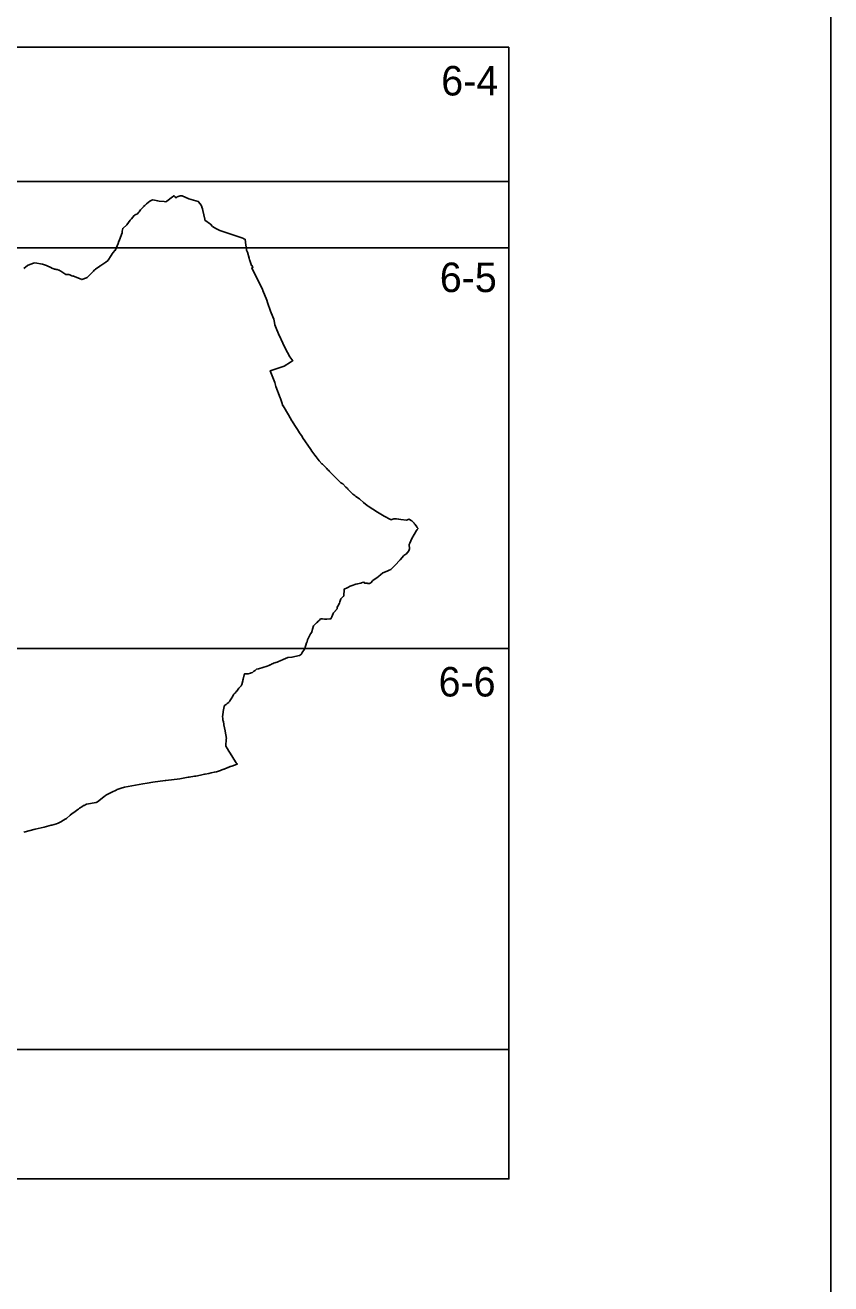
# Model space of a CAD drawing. Extents: x -449577 to -436680, y -1132317 to -1125726.
# Drawn here: x -443806.9 to -443555.6, y -1130335.5 to -1129943.1 of the extents above; entities that cross this region are included whole.
import ezdxf

# ---------------------------------------------------------------- set-up
doc = ezdxf.new("R2010")
doc.units = 0
for name, color, linetype in [('Vrstva 1', 7, 'Continuous'), ('Vrstva 10', 7, 'Continuous'), ('Vrstva 4', 7, 'Continuous')]:
    doc.layers.add(name, color=color, linetype=linetype)

msp = doc.modelspace()

# ---------------------------------------------------------------- linework, layer by layer
at = {"layer": 'Vrstva 1'}
msp.add_lwpolyline([(-445040.56, -1129648.53), (-445040.56, -1130698.53), (-443555.56, -1130698.53), (-443555.56, -1129648.53)], close=True, dxfattribs=at)
msp.add_lwpolyline([(-443807.27, -1130194.65), (-443803.73, -1130193.78), (-443800.96, -1130193.11), (-443800.29, -1130192.9), (-443798.8, -1130192.54), (-443798.59, -1130192.48), (-443797.16, -1130192.09), (-443796.56, -1130191.83), (-443796.34, -1130191.73), (-443796.18, -1130191.67), (-443795.36, -1130191.22), (-443795.3, -1130191.18), (-443793.99, -1130190.4), (-443792.84, -1130189.35), (-443792.19, -1130188.85), (-443792.06, -1130188.74), (-443792.04, -1130188.73), (-443791.88, -1130188.6), (-443791.73, -1130188.5), (-443790.93, -1130187.94), (-443790.87, -1130187.9), (-443790.8, -1130187.85), (-443790.29, -1130187.5), (-443789.92, -1130187.24), (-443789.26, -1130186.78), (-443788.67, -1130186.37), (-443788.51, -1130186.4), (-443788.5, -1130186.4), (-443788.48, -1130186.38), (-443787.75, -1130185.99), (-443784.79, -1130185.41), (-443784.37, -1130185.26), (-443782.34, -1130183.63), (-443781.87, -1130183.29), (-443781.84, -1130183.27), (-443781.48, -1130183.01), (-443781.3, -1130182.89), (-443779.91, -1130182.19), (-443778.5, -1130181.55), (-443778.2, -1130181.4), (-443776.94, -1130180.94), (-443775.94, -1130180.69), (-443770.23, -1130179.63), (-443768.81, -1130179.37), (-443767.1, -1130179.12), (-443763.23, -1130178.55), (-443762.99, -1130178.52), (-443758.69, -1130178), (-443758.16, -1130177.94), (-443756.01, -1130177.58), (-443755.69, -1130177.53), (-443754.03, -1130177.26), (-443753.63, -1130177.19), (-443752.22, -1130176.9), (-443750.93, -1130176.63), (-443750.72, -1130176.59), (-443749.55, -1130176.36), (-443748.88, -1130176.23), (-443748.86, -1130176.23), (-443747.95, -1130176.02), (-443747.88, -1130176), (-443747.23, -1130175.84), (-443746.88, -1130175.73), (-443745.99, -1130175.44), (-443745.55, -1130175.29), (-443744.9, -1130175.05), (-443744.78, -1130175.01), (-443743.69, -1130174.52), (-443743.69, -1130174.52), (-443743.57, -1130174.48), (-443742.92, -1130174.25), (-443742.83, -1130174.22), (-443742.4, -1130174.06), (-443740.74, -1130173.48), (-443740.76, -1130173.43), (-443740.87, -1130173.26), (-443741.03, -1130173.03), (-443741.25, -1130172.71), (-443742.95, -1130170.07), (-443743.16, -1130169.72), (-443743.33, -1130169.45), (-443743.77, -1130168.74), (-443744.3, -1130167.89), (-443744.14, -1130165.53), (-443744.13, -1130165.44), (-443744.52, -1130163.14), (-443744.52, -1130163.12), (-443744.53, -1130163.1), (-443744.53, -1130163.1), (-443744.53, -1130163.07), (-443744.94, -1130161.24), (-443744.95, -1130161.05), (-443745.01, -1130160.25), (-443745.11, -1130159.97), (-443745.12, -1130159.95), (-443745.23, -1130159.73), (-443745.27, -1130159.65), (-443745.28, -1130159.27), (-443745.31, -1130158.57), (-443745.26, -1130158.08), (-443745.26, -1130158.06), (-443745.17, -1130157.2), (-443745.15, -1130157.09), (-443744.86, -1130155.45), (-443744.78, -1130155.37), (-443744.48, -1130155.03), (-443744.42, -1130154.96), (-443744.16, -1130154.84), (-443744.1, -1130154.78), (-443743.84, -1130154.58), (-443743.61, -1130154.4), (-443743.4, -1130154.24), (-443743.34, -1130154.2), (-443743.26, -1130154.07), (-443743.18, -1130153.95), (-443743.07, -1130153.78), (-443742.85, -1130153.45), (-443742.43, -1130152.8), (-443742.3, -1130152.55), (-443742.29, -1130152.54), (-443742.15, -1130152.25), (-443742.1, -1130152.16), (-443741.92, -1130151.83), (-443741.78, -1130151.68), (-443741.48, -1130151.37), (-443741.31, -1130151.19), (-443741.03, -1130150.84), (-443740.9, -1130150.67), (-443740.21, -1130149.82), (-443739.55, -1130149.01), (-443739.26, -1130148.65), (-443739.02, -1130147.48), (-443738.96, -1130147.25), (-443738.89, -1130146.97), (-443738.57, -1130145.66), (-443738.49, -1130145.38), (-443738.49, -1130145.35), (-443738.47, -1130145.3), (-443738.31, -1130145.29), (-443738.29, -1130145.29), (-443738.05, -1130145.29), (-443737.36, -1130145.27), (-443737.35, -1130145.27), (-443737.32, -1130145.27), (-443736.64, -1130145.09), (-443736.44, -1130145.03), (-443736.02, -1130144.92), (-443736, -1130144.91), (-443735.94, -1130144.85), (-443735.64, -1130144.57), (-443735.52, -1130144.49), (-443735.18, -1130144.23), (-443734.76, -1130143.91), (-443734.69, -1130143.89), (-443734.13, -1130143.73), (-443731.43, -1130142.97), (-443730.84, -1130142.7), (-443730.51, -1130142.54), (-443730.46, -1130142.52), (-443730.36, -1130142.47), (-443730, -1130142.29), (-443729.95, -1130142.27), (-443729.92, -1130142.25), (-443729.91, -1130142.25), (-443729.88, -1130142.23), (-443729.57, -1130142.08), (-443729.51, -1130142.04), (-443729.4, -1130141.99), (-443728.32, -1130141.66), (-443727.89, -1130141.48), (-443727.37, -1130141.26), (-443726.36, -1130140.85), (-443724.94, -1130140.22), (-443724.8, -1130140.21), (-443723.67, -1130140.16), (-443721.27, -1130139.6), (-443720.74, -1130139.2), (-443720.67, -1130139.08), (-443720.58, -1130138.9), (-443720.32, -1130138.39), (-443719.97, -1130137.96), (-443719.95, -1130137.93), (-443719.74, -1130137.64), (-443719.63, -1130137.48), (-443719.62, -1130137.47), (-443719.08, -1130135.69), (-443719.07, -1130135.66), (-443718.87, -1130134.71), (-443718.61, -1130134.25), (-443718.42, -1130133.92), (-443717.87, -1130132.8), (-443717.49, -1130132.29), (-443717.46, -1130132.16), (-443717.39, -1130131.86), (-443717.36, -1130131.72), (-443717.3, -1130131.47), (-443717.28, -1130131.37), (-443716.96, -1130130.36), (-443716.95, -1130130.35), (-443716.66, -1130130.07), (-443716, -1130129.44), (-443715.95, -1130129.39), (-443715.48, -1130128.91), (-443715.22, -1130128.65), (-443715.12, -1130128.54), (-443714.75, -1130128.22), (-443714.71, -1130128.22), (-443714.7, -1130128.22), (-443714.29, -1130128.21), (-443714.12, -1130128.22), (-443713.49, -1130128.24), (-443712.78, -1130128.24), (-443711.81, -1130128.15), (-443711.78, -1130128.15), (-443711.53, -1130128.12), (-443711.31, -1130127.76), (-443711.26, -1130127.63), (-443711.24, -1130127.58), (-443711.22, -1130127.52), (-443710.86, -1130126.5), (-443710.72, -1130126.33), (-443710.62, -1130126.22), (-443710.58, -1130126.18), (-443710.52, -1130126.1), (-443710.4, -1130125.97), (-443710.13, -1130125.65), (-443710.04, -1130125.55), (-443709.94, -1130125.43), (-443709.6, -1130125.04), (-443709.53, -1130124.65), (-443709.47, -1130124.34), (-443709.4, -1130124.21), (-443708.85, -1130123.29), (-443708.74, -1130122.9), (-443708.55, -1130122.2), (-443708.43, -1130121.91), (-443708.14, -1130121.64), (-443707.59, -1130121.13), (-443707.52, -1130121.07), (-443707.42, -1130118.96), (-443706.4, -1130118.47), (-443706, -1130118.26), (-443705.75, -1130118.13), (-443705.46, -1130117.97), (-443705.24, -1130117.89), (-443704.9, -1130117.76), (-443704.85, -1130117.75), (-443703.76, -1130117.34), (-443703.75, -1130117.34), (-443703.26, -1130117.28), (-443703.18, -1130117.26), (-443702.15, -1130117), (-443702, -1130116.96), (-443701.91, -1130116.93), (-443701.74, -1130116.88), (-443701.21, -1130116.71), (-443701.21, -1130116.71), (-443701.2, -1130116.72), (-443701.2, -1130116.72), (-443701.17, -1130116.78), (-443701.04, -1130117), (-443700.16, -1130117.1), (-443699.96, -1130117.12), (-443699.6, -1130117.16), (-443699.51, -1130117.12), (-443699.08, -1130116.94), (-443698.43, -1130116.23), (-443696.79, -1130115.07), (-443696.7, -1130115), (-443696.53, -1130114.89), (-443696.02, -1130114.47), (-443695.27, -1130113.87), (-443694, -1130113.3), (-443693.38, -1130113.03), (-443692.84, -1130112.79), (-443692.78, -1130112.76), (-443691.13, -1130111.09), (-443690.29, -1130110.2), (-443689.93, -1130109.82), (-443688.74, -1130108.46), (-443688.14, -1130108), (-443688.09, -1130107.96), (-443687.25, -1130106.95), (-443687.05, -1130106.38), (-443687.14, -1130105.05), (-443686.92, -1130104.56), (-443686.28, -1130103.11), (-443684.82, -1130100.63), (-443684.79, -1130100.58), (-443684.79, -1130100.58), (-443684.77, -1130100.55), (-443684.74, -1130100.51), (-443684.59, -1130100.32), (-443684.33, -1130099.98), (-443684.59, -1130099.68), (-443684.73, -1130099.46), (-443685.2, -1130098.72), (-443685.4, -1130098.53), (-443685.55, -1130098.37), (-443685.74, -1130098.17), (-443686.32, -1130097.6), (-443687.17, -1130097.13), (-443687.62, -1130097.31), (-443687.95, -1130097.43), (-443689.7, -1130097.16), (-443690.31, -1130097.07), (-443690.45, -1130097.06), (-443691.04, -1130097.04), (-443691.42, -1130096.99), (-443691.58, -1130096.96), (-443691.62, -1130096.96), (-443691.65, -1130096.95), (-443691.65, -1130096.95), (-443691.68, -1130096.96), (-443691.78, -1130096.99), (-443691.91, -1130097.02), (-443692.81, -1130097.26), (-443692.88, -1130097.23), (-443694.95, -1130096.19), (-443696.97, -1130094.91), (-443699.88, -1130093.09), (-443700.04, -1130092.95), (-443700.08, -1130092.92), (-443700.17, -1130092.84), (-443701.31, -1130091.91), (-443702.46, -1130090.86), (-443702.57, -1130090.76), (-443703.78, -1130090), (-443704.06, -1130089.77), (-443704.69, -1130089.27), (-443705, -1130089.03), (-443705.5, -1130088.5), (-443706.22, -1130087.74), (-443706.37, -1130087.58), (-443706.83, -1130087.09), (-443707.8, -1130086.06), (-443708, -1130085.95), (-443708, -1130085.95), (-443708.18, -1130085.86), (-443708.38, -1130085.76), (-443709.21, -1130084.93), (-443709.84, -1130084.3), (-443711.02, -1130083.13), (-443711.95, -1130082.19), (-443712.11, -1130082.04), (-443712.55, -1130081.59), (-443712.79, -1130081.35), (-443712.88, -1130081.26), (-443712.92, -1130081.22), (-443713.44, -1130080.7), (-443714.08, -1130080.05), (-443714.16, -1130079.97), (-443714.18, -1130079.95), (-443714.33, -1130079.8), (-443715.16, -1130078.96), (-443715.54, -1130078.46), (-443715.82, -1130078.09), (-443716.14, -1130077.66), (-443716.5, -1130077.18), (-443717.45, -1130075.92), (-443717.82, -1130075.38), (-443720.36, -1130071.64), (-443720.53, -1130071.38), (-443721.3, -1130070.19), (-443721.97, -1130069.18), (-443722.81, -1130067.85), (-443723.61, -1130066.58), (-443723.69, -1130066.45), (-443724.78, -1130064.6), (-443726.46, -1130061.75), (-443726.46, -1130061.74), (-443726.46, -1130061.74), (-443726.47, -1130061.74), (-443726.8, -1130060.76), (-443727.25, -1130059.46), (-443727.31, -1130059.26), (-443728.69, -1130055.75), (-443728.98, -1130054.5), (-443730.46, -1130050.82), (-443729.83, -1130050.62), (-443726.11, -1130049.38), (-443724.14, -1130048.16), (-443723.96, -1130048.05), (-443723.9, -1130048.01), (-443723.7, -1130047.89), (-443723.43, -1130047.72), (-443724.35, -1130046.53), (-443725.76, -1130043.75), (-443726.51, -1130042.28), (-443727.04, -1130041.12), (-443727.06, -1130041.08), (-443727.12, -1130040.95), (-443727.13, -1130040.92), (-443727.15, -1130040.89), (-443727.19, -1130040.8), (-443727.52, -1130040.07), (-443727.84, -1130039.28), (-443728.55, -1130037.51), (-443728.96, -1130036.47), (-443729.11, -1130035.84), (-443729.37, -1130034.71), (-443730.11, -1130032.82), (-443730.31, -1130032.22), (-443731.25, -1130029.59), (-443731.52, -1130028.87), (-443732.71, -1130025.78), (-443732.78, -1130025.6), (-443732.81, -1130025.52), (-443736.16, -1130018.71), (-443735.85, -1130018.57), (-443735.83, -1130018.56), (-443735.93, -1130018.39), (-443736.01, -1130018.29), (-443736.18, -1130018.06), (-443736.24, -1130017.98), (-443736.85, -1130016.5), (-443736.9, -1130016.21), (-443737, -1130015.75), (-443737.01, -1130015.69), (-443737.52, -1130013.85), (-443737.82, -1130013.22), (-443737.83, -1130013.14), (-443737.87, -1130012.78), (-443738.01, -1130011.69), (-443738.29, -1130009.85), (-443738.35, -1130009.83), (-443738.65, -1130009.73), (-443739.03, -1130009.47), (-443739.04, -1130009.47), (-443743.34, -1130008.06), (-443746.13, -1130007.08), (-443747.44, -1130006.46), (-443748.41, -1130005.9), (-443749.13, -1130005.12), (-443750.81, -1130003.85), (-443750.87, -1130003.55), (-443751.45, -1130000.85), (-443751.6, -1130000.31), (-443751.78, -1129999.8), (-443751.83, -1129999.64), (-443752.08, -1129999.12), (-443752.33, -1129998.81), (-443752.91, -1129998.12), (-443753.66, -1129997.91), (-443755.84, -1129997.25), (-443757.93, -1129996.29), (-443758.55, -1129996.29), (-443759.5, -1129996.66), (-443759.63, -1129996.75), (-443759.7, -1129996.8), (-443759.84, -1129996.9), (-443759.88, -1129996.93), (-443759.9, -1129996.91), (-443760.11, -1129996.66), (-443760.36, -1129996.38), (-443760.44, -1129996.28), (-443760.53, -1129996.32), (-443761.04, -1129996.71), (-443761.23, -1129996.86), (-443761.9, -1129997.38), (-443762.65, -1129997.94), (-443762.99, -1129998.16), (-443763.58, -1129998.12), (-443765.06, -1129997.97), (-443765.52, -1129997.88), (-443767.11, -1129997.56), (-443767.41, -1129997.67), (-443767.97, -1129998.02), (-443768.52, -1129998.34), (-443769.01, -1129998.8), (-443769.54, -1129999.29), (-443769.94, -1129999.68), (-443769.95, -1129999.69), (-443770.28, -1130000.03), (-443770.41, -1130000.17), (-443770.92, -1130000.72), (-443771.37, -1130001.27), (-443771.53, -1130001.46), (-443771.89, -1130001.89), (-443772.63, -1130002.22), (-443772.65, -1130002.22), (-443772.85, -1130002.47), (-443773.71, -1130003.49), (-443774.09, -1130003.94), (-443775.22, -1130005.3), (-443775.23, -1130005.31), (-443776.47, -1130006.48), (-443776.59, -1130007.32), (-443776.64, -1130007.69), (-443776.68, -1130007.79), (-443777.16, -1130009.14), (-443777.6, -1130010.38), (-443777.63, -1130010.46), (-443777.93, -1130011.15), (-443778.86, -1130013.33), (-443778.88, -1130013.34), (-443779.45, -1130014.02), (-443779.75, -1130014.37), (-443779.75, -1130014.38), (-443780.09, -1130014.92), (-443780.96, -1130016.31), (-443781.05, -1130016.45), (-443781.22, -1130016.58), (-443781.75, -1130016.97), (-443782.36, -1130017.42), (-443782.36, -1130017.42), (-443783.33, -1130018.05), (-443783.46, -1130018.14), (-443783.64, -1130018.26), (-443784.94, -1130019.12), (-443784.95, -1130019.13), (-443785.21, -1130019.39), (-443785.33, -1130019.51), (-443785.55, -1130019.74), (-443785.83, -1130020.02), (-443786.4, -1130020.59), (-443787.56, -1130021.75), (-443787.76, -1130021.83), (-443789.26, -1130022.4), (-443792.07, -1130021.28), (-443792.07, -1130021.29), (-443792.08, -1130021.31), (-443792.99, -1130020.93), (-443793.3, -1130020.8), (-443793.32, -1130020.8), (-443793.71, -1130020.8), (-443794.19, -1130020.8), (-443795.75, -1130019.81), (-443796.01, -1130019.68), (-443796.3, -1130019.52), (-443796.36, -1130019.49), (-443796.4, -1130019.47), (-443796.94, -1130019.24), (-443796.99, -1130019.24), (-443797, -1130019.24), (-443797.15, -1130019.23), (-443797.27, -1130019.22), (-443797.58, -1130019.2), (-443797.6, -1130019.2), (-443797.6, -1130019.2), (-443797.71, -1130019.16), (-443797.95, -1130019.06), (-443798.55, -1130018.81), (-443798.71, -1130018.74), (-443800.23, -1130018.01), (-443800.85, -1130017.83), (-443801.52, -1130017.63), (-443803.84, -1130017.2), (-443803.85, -1130017.2), (-443804.25, -1130017.31), (-443805.99, -1130017.89), (-443806.12, -1130018), (-443807.33, -1130018.96)], dxfattribs=at)
at = {"layer": 'Vrstva 10'}
msp.add_lwpolyline([(-443655.97, -1129991.79), (-443655.97, -1130302.77), (-443988.84, -1130302.77), (-443988.84, -1130137.47), (-443968.47, -1130137.47), (-443968.47, -1130012.47), (-443968.47, -1129991.79), (-443655.97, -1129991.79)], dxfattribs=at)
at = {"layer": 'Vrstva 4'}
msp.add_line((-443968.47, -1129949.97), (-443655.97, -1129949.97), dxfattribs=at)
msp.add_lwpolyline([(-443655.97, -1129949.97), (-443655.97, -1130012.47), (-443812.22, -1130012.47), (-443812.22, -1129949.97)], dxfattribs=at)
for points in [[(-443655.97, -1130012.47), (-443655.97, -1130137.47), (-443812.22, -1130137.47), (-443812.22, -1130012.47)], [(-443655.97, -1130137.47), (-443655.97, -1130262.47), (-443812.22, -1130262.47), (-443812.22, -1130137.47)]]:
    msp.add_lwpolyline(points, close=True, dxfattribs=at)

# ---------------------------------------------------------------- texts
at = {"layer": 'Vrstva 1'}
for s, p in [('6-4', (-443677.1, -1129965.02)), ('6-5', (-443677.55, -1130026.31)), ('6-6', (-443677.92, -1130152.38))]:
    msp.add_text(s, height=9.2, dxfattribs=at).set_placement(p)

doc.saveas('drawing.dxf')
